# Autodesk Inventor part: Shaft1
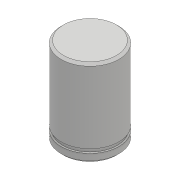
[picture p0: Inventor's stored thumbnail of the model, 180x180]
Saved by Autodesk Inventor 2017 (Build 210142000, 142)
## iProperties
Created: 2016-07
Part Number: Shaft1
Material: Generic
Document SubType Name: Modeling
Designer: Sandeep
Density: 1 g/cm^3
Appearance: Default
Author: Sandeep
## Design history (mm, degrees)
sketch "Sketch1"
  geometry: L1 (0, 81.023)-(0, 0); L2 (0, 75)-(25, 75); L3 (25, 75)-(25, 11.018); L4 (25, 11.018)-(23.5, 11.018); L5 (23.5, 11.018)-(23.5, 7.5); L6 (23.5, 7.5)-(25, 7.5); L7 (25, 7.5)-(25, 0); L8 (25, 0)-(0, 0); L9 (0, 0)-(0, 75)
  constraints: 18 end point, 5 perpendicular, 5 point on line, 1 horizontal, 1 vertical
  dimensions: "d0" = 50 diameter of L3 L1; "d1" = 47 diameter of L5 L1; "d2" = 7.5 distance between parallel lines of L8 L6; "d3" = 75 distance between parallel lines of L8 L2
revolve "Revolution1" sketch "Sketch1" stored, may be unused: angle "d4" = 90 deg
chamfer "Chamfer1" distance "d5" = 2; stored, may be unused: second distance "d6" = 2, angle "d7" = 45 deg
chamfer "Chamfer2" distance "d8" = 2; stored, may be unused: second distance "d9" = 2, angle "d10" = 45 deg
body "Solid1"
